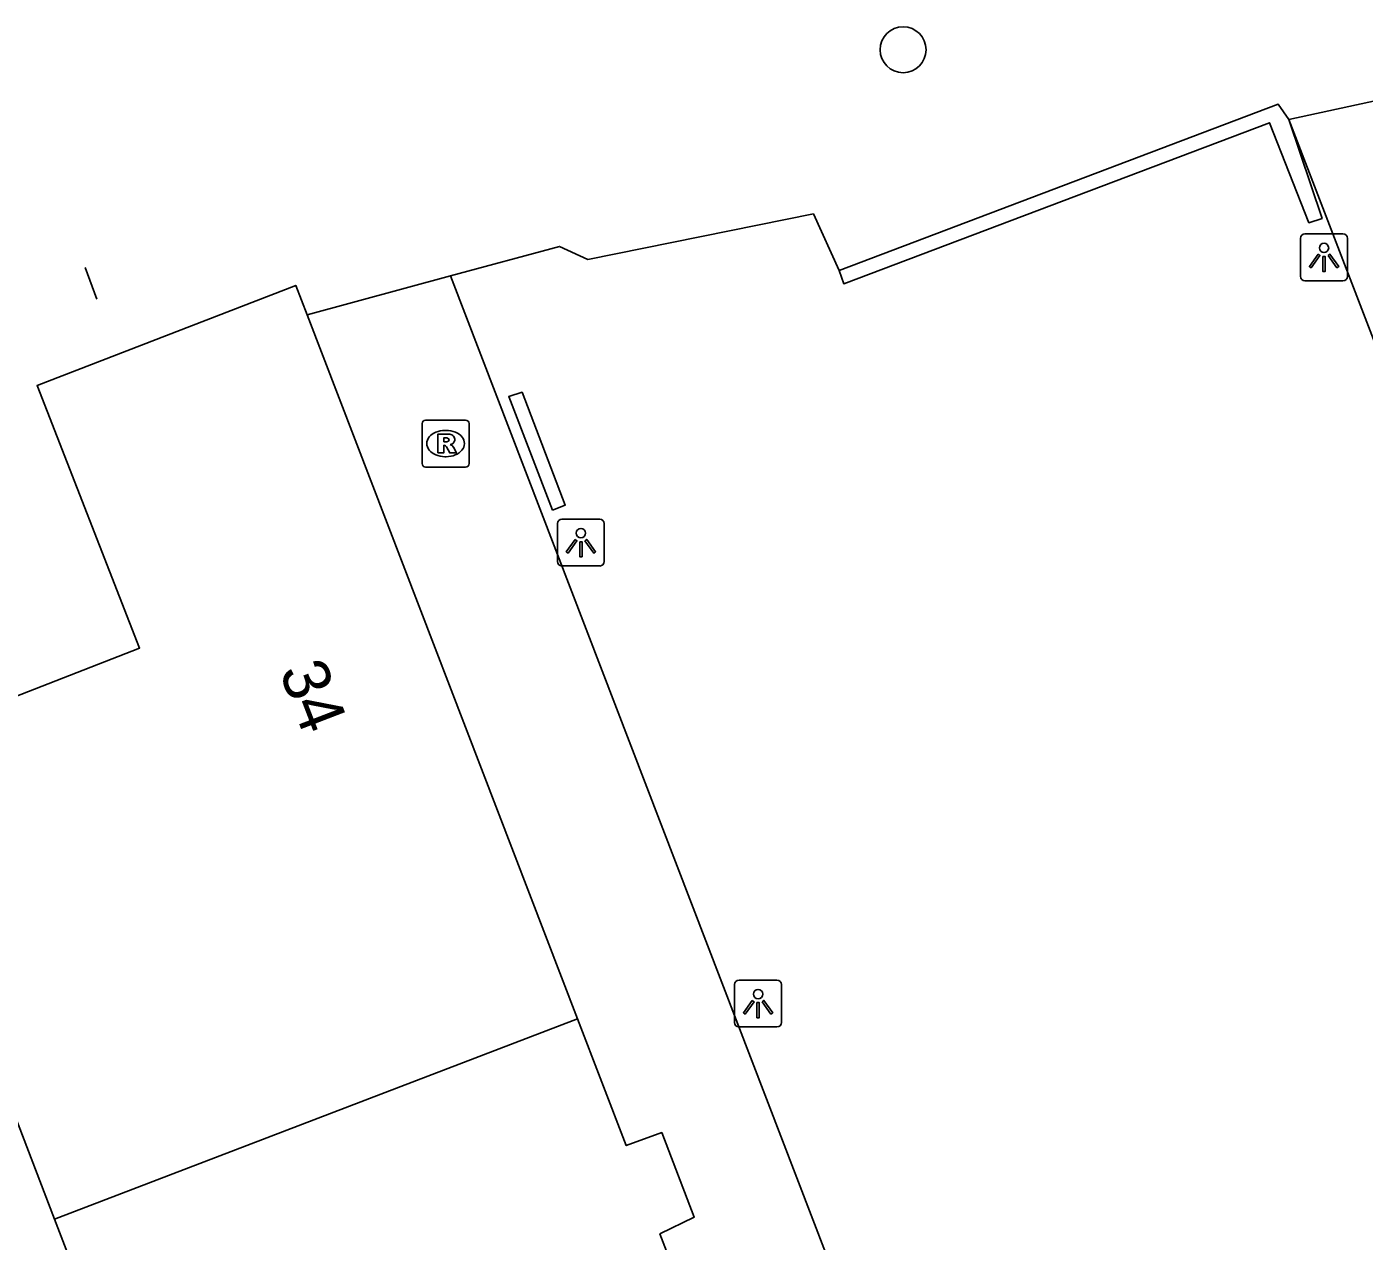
# Model space of a CAD drawing. Extents: x 159265 to 160143, y 383413 to 384319.
# Drawn here: x 159559.73 to 159588.18, y 383700.91 to 383726.76 of the extents above; entities that cross this region are included whole.
import ezdxf

# ---------------------------------------------------------------- set-up
doc = ezdxf.new("R2010")
doc.units = 0
for name, color, linetype in [('IMGEO_Boom', 7, 'Continuous'), ('IMGEO_Hek', 7, 'Continuous'), ('IMGEO_Lichtpunt', 7, 'Continuous'), ('IMGEO_Muur', 7, 'Continuous'), ('IMGEO_Pand', 7, 'Continuous'), ('IMGEO_Pand_nummerreeks', 7, 'Continuous'), ('IMGEO_Rioolput', 7, 'Continuous'), ('IMGEO_Voetpad_gesloten', 7, 'Continuous'), ('IMGEO_Voetpad_open', 7, 'Continuous')]:
    doc.layers.add(name, color=color, linetype=linetype)

msp = doc.modelspace()

# ---------------------------------------------------------------- linework, layer by layer
at = {"layer": 'IMGEO_Boom'}
msp.add_circle((159578.372, 383726.271), 0.489, dxfattribs=at)
at = {"layer": 'IMGEO_Hek'}
msp.add_lwpolyline([(159561.216, 383720.958), (159560.969, 383721.634)], dxfattribs=at)
at = {"layer": 'IMGEO_Lichtpunt'}
for p, q in [((159586.828, 383722.255), (159586.828, 383721.448)), ((159586.828, 383722.255), (159586.828, 383721.448)), ((159587.73, 383722.35), (159586.922, 383722.35)), ((159587.73, 383722.35), (159586.922, 383722.35)), ((159587.824, 383721.448), (159587.824, 383722.255)), ((159587.824, 383721.448), (159587.824, 383722.255)), ((159586.922, 383721.354), (159587.73, 383721.354)), ((159586.922, 383721.354), (159587.73, 383721.354)), ((159571.017, 383716.182), (159571.017, 383715.375)), ((159571.017, 383716.182), (159571.017, 383715.375)), ((159571.919, 383716.277), (159571.111, 383716.277)), ((159571.919, 383716.277), (159571.111, 383716.277)), ((159572.013, 383715.375), (159572.013, 383716.182)), ((159572.013, 383715.375), (159572.013, 383716.182)), ((159571.111, 383715.281), (159571.919, 383715.281)), ((159571.111, 383715.281), (159571.919, 383715.281)), ((159574.786, 383706.369), (159574.786, 383705.562)), ((159574.786, 383706.369), (159574.786, 383705.562)), ((159575.688, 383706.464), (159574.88, 383706.464)), ((159575.688, 383706.464), (159574.88, 383706.464)), ((159575.782, 383705.562), (159575.782, 383706.369)), ((159575.782, 383705.562), (159575.782, 383706.369)), ((159574.88, 383705.468), (159575.688, 383705.468)), ((159574.88, 383705.468), (159575.688, 383705.468))]:
    msp.add_line(p, q, dxfattribs=at)
for points in [[(159587.202, 383721.919), (159587.241, 383721.891), (159587.053, 383721.629), (159587.015, 383721.656), (159587.202, 383721.919)], [(159587.304, 383721.871), (159587.351, 383721.871), (159587.351, 383721.549), (159587.304, 383721.549), (159587.304, 383721.871)], [(159587.414, 383721.891), (159587.452, 383721.918), (159587.639, 383721.656), (159587.6, 383721.628), (159587.414, 383721.891)], [(159571.391, 383715.846), (159571.43, 383715.818), (159571.242, 383715.556), (159571.204, 383715.583), (159571.391, 383715.846)], [(159571.493, 383715.798), (159571.54, 383715.798), (159571.54, 383715.476), (159571.493, 383715.476), (159571.493, 383715.798)], [(159571.603, 383715.818), (159571.641, 383715.845), (159571.828, 383715.583), (159571.789, 383715.555), (159571.603, 383715.818)], [(159575.16, 383706.033), (159575.199, 383706.005), (159575.011, 383705.743), (159574.973, 383705.77), (159575.16, 383706.033)], [(159575.262, 383705.985), (159575.309, 383705.985), (159575.309, 383705.663), (159575.262, 383705.663), (159575.262, 383705.985)], [(159575.372, 383706.005), (159575.41, 383706.032), (159575.597, 383705.77), (159575.558, 383705.742), (159575.372, 383706.005)]]:
    msp.add_lwpolyline(points, dxfattribs=at)
for centre in [(159587.327, 383722.053), (159571.516, 383715.98), (159575.285, 383706.167)]:
    msp.add_circle(centre, 0.0994, dxfattribs=at)
for centre, start, end in [((159586.922, 383722.255), 90, 180), ((159586.922, 383722.255), 90, 180), ((159587.73, 383722.255), 0, 90), ((159587.73, 383722.255), 0, 90), ((159586.922, 383721.448), 180, 270), ((159586.922, 383721.448), 180, 270), ((159587.73, 383721.448), 270, 0), ((159587.73, 383721.448), 270, 360), ((159571.111, 383716.182), 90, 180), ((159571.111, 383716.182), 90, 180), ((159571.919, 383716.182), 0, 90), ((159571.919, 383716.182), 0, 90), ((159571.111, 383715.375), 180, 270), ((159571.111, 383715.375), 180, 270), ((159571.919, 383715.375), 270, 0), ((159571.919, 383715.375), 270, 360), ((159574.88, 383706.369), 90, 180), ((159574.88, 383706.369), 90, 180), ((159575.688, 383706.369), 0, 90), ((159575.688, 383706.369), 0, 90), ((159574.88, 383705.562), 180, 270), ((159574.88, 383705.562), 180, 270), ((159575.688, 383705.562), 270, 0), ((159575.688, 383705.562), 270, 360)]:
    msp.add_arc(centre, 0.0946, start, end, dxfattribs=at)
at = {"layer": 'IMGEO_Muur'}
for points in [[(159577.009, 383721.57), (159586.348, 383725.115), (159586.575, 383724.788)], [(159586.575, 383724.788), (159587.285, 383722.681), (159587.007, 383722.588), (159586.168, 383724.718), (159577.11, 383721.288), (159577.009, 383721.57)], [(159570.913, 383716.468), (159569.981, 383718.887), (159570.265, 383718.978), (159571.182, 383716.579), (159570.913, 383716.468)]]:
    msp.add_lwpolyline(points, dxfattribs=at)
at = {"layer": 'IMGEO_Pand'}
for points in [[(159559.356, 383703.878), (159557.383, 383709.005), (159555.583, 383708.345), (159553.157, 383714.756), (159554.929, 383715.449), (159556.489, 383711.329), (159562.125, 383713.533), (159559.946, 383719.125), (159565.449, 383721.255), (159565.691, 383720.625)], [(159565.691, 383720.625), (159571.446, 383705.64)], [(159571.446, 383705.64), (159560.318, 383701.375)], [(159575.419, 383695.279), (159573.198, 383701.061), (159573.927, 383701.421), (159573.236, 383703.219), (159572.482, 383702.942), (159571.446, 383705.64)], [(159560.318, 383701.375), (159559.356, 383703.878)], [(159560.318, 383701.375), (159564.264, 383691.107)]]:
    msp.add_lwpolyline(points, dxfattribs=at)
at = {"layer": 'IMGEO_Rioolput'}
for p, q in [((159568.137, 383717.461), (159568.137, 383718.313)), ((159568.212, 383718.387), (159569.064, 383718.387)), ((159568.625, 383718.167), (159568.65, 383718.167)), ((159569.138, 383718.313), (159569.138, 383717.461)), ((159568.648, 383717.607), (159568.623, 383717.607)), ((159569.064, 383717.387), (159568.212, 383717.387))]:
    msp.add_line(p, q, dxfattribs=at)
for points in [[(159568.137, 383717.461), (159568.137, 383718.313)], [(159568.212, 383718.387), (159569.064, 383718.387)], [(159569.138, 383718.313), (159569.138, 383717.461)], [(159568.726, 383718.085), (159568.474, 383718.087), (159568.474, 383717.687)], [(159568.652, 383718.006), (159568.598, 383718.006), (159568.598, 383717.925)], [(159568.598, 383717.925), (159568.65, 383717.925)], [(159568.474, 383717.687), (159568.598, 383717.687), (159568.598, 383717.849), (159568.609, 383717.849)], [(159568.656, 383717.82), (159568.727, 383717.687), (159568.867, 383717.687), (159568.802, 383717.813)], [(159569.064, 383717.387), (159568.212, 383717.387)]]:
    msp.add_lwpolyline(points, dxfattribs=at)
for centre, radius, start, end in [((159568.214, 383718.311), 0.0765, 91.552, 178.448), ((159568.214, 383718.311), 0.0765, 91.552, 178.448), ((159569.062, 383718.311), 0.0765, 1.552, 88.448), ((159569.062, 383718.311), 0.0765, 1.552, 88.448), ((159568.634, 383718.114), 0.19, 274.7715, 282.9687), ((159568.658, 383717.91), 0.0964, 77.0061, 93.1865), ((159568.672, 383717.967), 0.0378, 276.6634, 79.6772), ((159568.725, 383717.975), 0.109, 350.3612, 89.416), ((159568.723, 383717.975), 0.112, 277.5842, 350.9817), ((159568.608, 383717.796), 0.0533, 26.0293, 88.6989), ((159568.707, 383717.76), 0.108, 29.5134, 73.7905), ((159568.214, 383717.463), 0.0765, 181.552, 268.448), ((159568.214, 383717.463), 0.0765, 181.552, 268.448), ((159569.062, 383717.463), 0.0765, 271.552, 358.448), ((159569.062, 383717.463), 0.0765, 271.552, 358.448)]:
    msp.add_arc(centre, radius, start, end, dxfattribs=at)
for centre, major_axis, ratio, start_param, end_param in [((159568.624, 383717.887), (-0.387, 0.002), 0.722429, 4.712389, 7.853982), ((159568.649, 383717.887), (-0.39, 0.002), 0.717154, 1.570796, 4.712389)]:
    msp.add_ellipse(centre, major_axis=major_axis, ratio=ratio, start_param=start_param, end_param=end_param, dxfattribs=at)
at = {"layer": 'IMGEO_Voetpad_gesloten'}
for points in [[(159586.575, 383724.788), (159599.498, 383691.195)], [(159568.739, 383721.454), (159571.059, 383722.084), (159571.667, 383721.806), (159576.464, 383722.774), (159577.009, 383721.57)], [(159568.739, 383721.454), (159580.594, 383690.575)]]:
    msp.add_lwpolyline(points, dxfattribs=at)
at = {"layer": 'IMGEO_Voetpad_open'}
for points in [[(159586.575, 383724.788), (159589.98, 383725.525), (159592.463, 383719.183)], [(159565.691, 383720.625), (159568.739, 383721.454)]]:
    msp.add_lwpolyline(points, dxfattribs=at)

# ---------------------------------------------------------------- texts
at = {"layer": 'IMGEO_Pand_nummerreeks'}
msp.add_text('34', height=1, rotation=291.0109, dxfattribs=at).set_placement((159565.09, 383713.04))

doc.saveas('drawing.dxf')
